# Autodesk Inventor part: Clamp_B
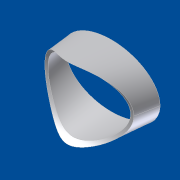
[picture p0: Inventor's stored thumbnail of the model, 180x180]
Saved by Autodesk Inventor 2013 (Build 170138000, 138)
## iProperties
Shininess: 64.0
Length Units: 11269
Angle Units: 11279
Time Units: 11290
Mass Units: 11283
Length Display Precision: 3
Angle Display Precision: 2
Compacted: True
Part Number: Clamp_B
Document SubType Name: Modeling
Created: 2002-10
Designer: roithn
Density: 1 g/cm^3
Material: Generic
Density: 0.0
Volumn: 0.0
Area: 0.0
PropertySet Name: Model Information
Control State: 0
Master: False
Checked Out: False
Author: roithn
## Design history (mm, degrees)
sketch "Sketch1"
  geometry: 1 further point; 1 other entity
  constraints: 1 other
  node "Reference1"
workplane "Work Plane1"
sketch "Sketch2"
  geometry: C1 r 17.5 at (0, 0); 1 further point; 1 other entity
  constraints: 1 centre point, 1 coincident, 1 other
  dimensions: "d0" = 35 diameter of C1
loft "Loft1" sketch "Sketch2" dims "d1" = 0, "d2" = 90 deg, "d3" = 0, "d4" = 90 deg
shell "Shell1" dims "d5" = 1.5
sketch "Sketch3"
  geometry: L1 (-17.5, 29.5)-(17.5, 29.5) reference; C1 r 19 at (0, 29.5); 1 further point
  constraints: 1 centre point, 1 coincident
extrude "Extrusion1" cut sketch "Sketch3" stored distance "d6" = 10; taper "d7" = 0 deg
body "Solid1"
node "Reference2"
